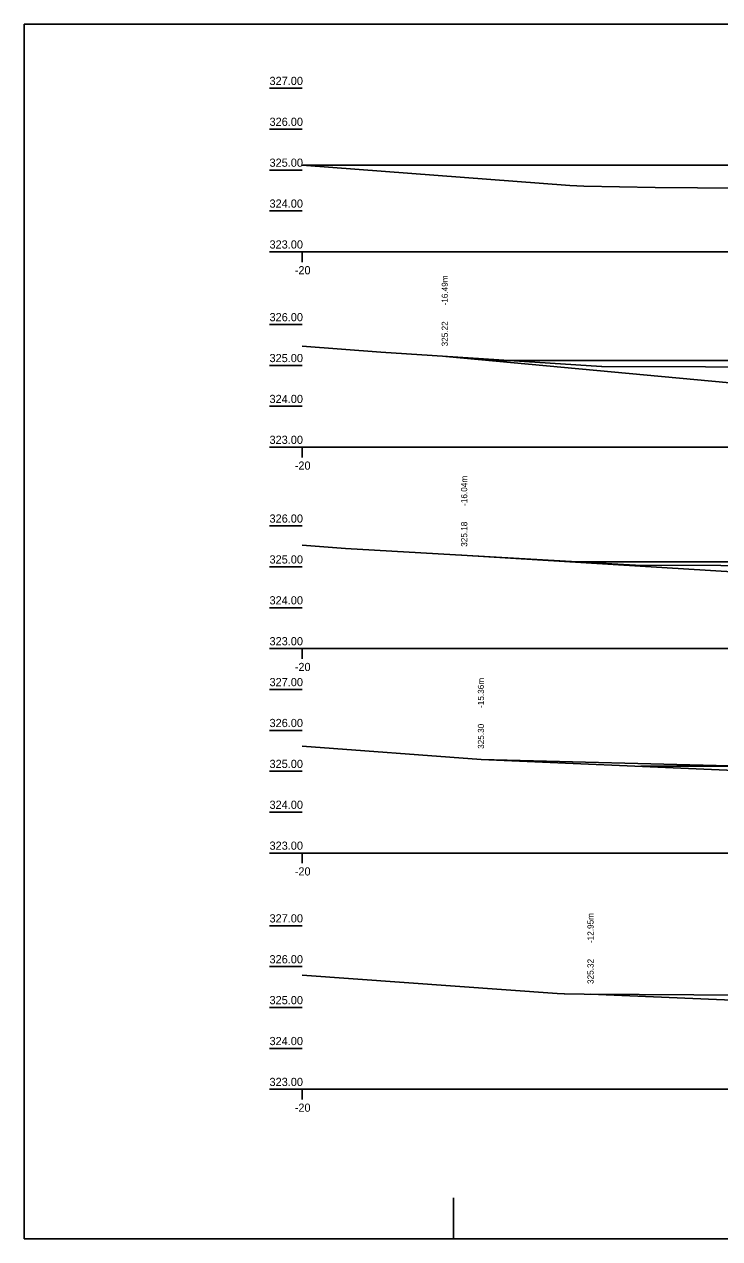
# Model space of a CAD drawing. Extents: x -557877.8 to -557804.3, y -1162285.8 to -1162256.1.
# Drawn here: x -557877.8 to -557860.8, y -1162285.8 to -1162256.1 of the extents above; entities that cross this region are included whole.
import ezdxf

# ---------------------------------------------------------------- set-up
doc = ezdxf.new("R2010")
doc.units = 0
for name, color, linetype in [('16', 7, 'Continuous'), ('21', 7, 'Continuous'), ('59', 7, 'Continuous'), ('Body pricny rez', 7, 'Continuous'), ('Popis pricneho profilu', 7, 'Continuous')]:
    doc.layers.add(name, color=color, linetype=linetype)

msp = doc.modelspace()

# ---------------------------------------------------------------- linework, layer by layer
for p, q in [((-557804.302, -1162256.102), (-557877.802, -1162256.102)), ((-557877.802, -1162256.102), (-557877.802, -1162285.802)), ((-557867.302, -1162285.802), (-557867.302, -1162284.802)), ((-557877.802, -1162285.802), (-557804.302, -1162285.802))]:
    msp.add_line(p, q)
for points in [[(-557871.005, -1162259.545), (-557864.464, -1162260.043), (-557864.118, -1162260.057), (-557862.37, -1162260.09), (-557859.263, -1162260.117), (-557856.183, -1162260.062), (-557856.133, -1162260.062), (-557856.051, -1162260.06), (-557848.291, -1162259.873), (-557847.829, -1162259.856), (-557840.415, -1162259.648), (-557840.07, -1162259.632), (-557832.415, -1162259.263), (-557831.005, -1162259.154)], [(-557870.994, -1162259.546), (-557838.275, -1162259.546)], [(-557871.005, -1162263.973), (-557869.084, -1162264.121), (-557863.687, -1162264.471), (-557863.682, -1162264.471), (-557861.146, -1162264.48), (-557859.312, -1162264.494), (-557859.307, -1162264.494), (-557857.717, -1162264.456), (-557856.24, -1162264.425), (-557852.539, -1162264.339), (-557848.349, -1162264.225), (-557844.087, -1162264.128), (-557840.375, -1162264.022), (-557836.581, -1162263.841), (-557832.414, -1162263.676), (-557831.005, -1162263.567)], [(-557854.045, -1162265.475), (-557867.49, -1162264.224)], [(-557866.422, -1162264.324), (-557839.401, -1162264.324)], [(-557871.005, -1162268.839), (-557869.944, -1162268.921), (-557862.864, -1162269.33), (-557862.864, -1162269.33), (-557862.858, -1162269.33), (-557860.77, -1162269.339), (-557859.335, -1162269.35), (-557859.329, -1162269.35), (-557857.423, -1162269.305), (-557856.259, -1162269.28), (-557853.342, -1162269.212), (-557848.362, -1162269.077), (-557843.297, -1162268.961), (-557840.368, -1162268.878), (-557837.376, -1162268.736), (-557832.408, -1162268.539), (-557831.005, -1162268.43)], [(-557854.281, -1162269.873), (-557867.102, -1162269.085)], [(-557864.436, -1162269.249), (-557841.875, -1162269.249)], [(-557871.005, -1162273.756), (-557866.633, -1162274.079), (-557866.633, -1162274.079), (-557866.626, -1162274.079), (-557860.248, -1162274.247), (-557859.367, -1162274.253), (-557859.359, -1162274.253), (-557857.014, -1162274.198), (-557856.286, -1162274.182), (-557854.46, -1162274.14), (-557848.38, -1162273.975), (-557842.196, -1162273.834), (-557840.359, -1162273.781), (-557838.482, -1162273.692), (-557832.4, -1162273.451), (-557831.005, -1162273.343)], [(-557854.611, -1162274.603), (-557866.633, -1162274.079)], [(-557862.728, -1162274.249), (-557841.132, -1162274.249)], [(-557871.005, -1162279.36), (-557864.773, -1162279.805), (-557864.6, -1162279.814), (-557864.591, -1162279.815), (-557864.11, -1162279.821), (-557860.084, -1162279.844), (-557860.076, -1162279.845), (-557857.908, -1162279.794), (-557856.326, -1162279.761), (-557848.559, -1162279.549), (-557848.413, -1162279.546), (-557848.274, -1162279.543), (-557840.34, -1162279.365), (-557839.969, -1162279.351), (-557832.396, -1162279.05), (-557831.005, -1162278.934)], [(-557855.288, -1162280.192), (-557863.955, -1162279.822)]]:
    msp.add_lwpolyline(points)
at = {"layer": '16'}
for p, q in [((-557871.005, -1162261.666), (-557831.005, -1162261.666)), ((-557871.005, -1162266.444), (-557831.005, -1162266.444)), ((-557871.005, -1162271.369), (-557831.005, -1162271.369)), ((-557871.005, -1162276.369), (-557831.005, -1162276.369)), ((-557871.005, -1162282.147), (-557831.005, -1162282.147))]:
    msp.add_line(p, q, dxfattribs=at)
at = {"layer": '21'}
for p, q in [((-557871.805, -1162257.666), (-557871.005, -1162257.666)), ((-557871.805, -1162258.666), (-557871.005, -1162258.666)), ((-557871.805, -1162259.666), (-557871.005, -1162259.666)), ((-557871.805, -1162260.666), (-557871.005, -1162260.666)), ((-557871.805, -1162261.666), (-557871.005, -1162261.666)), ((-557871.805, -1162263.444), (-557871.005, -1162263.444)), ((-557871.805, -1162264.444), (-557871.005, -1162264.444)), ((-557871.805, -1162265.444), (-557871.005, -1162265.444)), ((-557871.805, -1162266.444), (-557871.005, -1162266.444)), ((-557871.805, -1162268.369), (-557871.005, -1162268.369)), ((-557871.805, -1162269.369), (-557871.005, -1162269.369)), ((-557871.805, -1162270.369), (-557871.005, -1162270.369)), ((-557871.805, -1162271.369), (-557871.005, -1162271.369)), ((-557871.805, -1162272.369), (-557871.005, -1162272.369)), ((-557871.805, -1162273.369), (-557871.005, -1162273.369)), ((-557871.805, -1162274.369), (-557871.005, -1162274.369)), ((-557871.805, -1162275.369), (-557871.005, -1162275.369)), ((-557871.805, -1162276.369), (-557871.005, -1162276.369)), ((-557871.805, -1162278.147), (-557871.005, -1162278.147)), ((-557871.805, -1162279.147), (-557871.005, -1162279.147)), ((-557871.805, -1162280.147), (-557871.005, -1162280.147)), ((-557871.805, -1162281.147), (-557871.005, -1162281.147)), ((-557871.805, -1162282.147), (-557871.005, -1162282.147))]:
    msp.add_line(p, q, dxfattribs=at)
at = {"layer": '59'}
for p, q in [((-557871.005, -1162261.916), (-557871.005, -1162261.666)), ((-557871.005, -1162266.694), (-557871.005, -1162266.444)), ((-557871.005, -1162271.619), (-557871.005, -1162271.369)), ((-557871.005, -1162276.619), (-557871.005, -1162276.369)), ((-557871.005, -1162282.397), (-557871.005, -1162282.147))]:
    msp.add_line(p, q, dxfattribs=at)

# ---------------------------------------------------------------- texts
at = {"layer": '21'}
for s, p in [('327.00', (-557871.805, -1162257.586)), ('326.00', (-557871.805, -1162258.586)), ('325.00', (-557871.805, -1162259.586)), ('324.00', (-557871.805, -1162260.586)), ('323.00', (-557871.805, -1162261.586)), ('-20', (-557871.188, -1162262.216)), ('326.00', (-557871.805, -1162263.364)), ('325.00', (-557871.805, -1162264.364)), ('324.00', (-557871.805, -1162265.364)), ('323.00', (-557871.805, -1162266.364)), ('-20', (-557871.188, -1162266.994)), ('326.00', (-557871.805, -1162268.289)), ('325.00', (-557871.805, -1162269.289)), ('324.00', (-557871.805, -1162270.289)), ('323.00', (-557871.805, -1162271.289)), ('-20', (-557871.188, -1162271.919)), ('327.00', (-557871.805, -1162272.289)), ('326.00', (-557871.805, -1162273.289)), ('325.00', (-557871.805, -1162274.289)), ('324.00', (-557871.805, -1162275.289)), ('323.00', (-557871.805, -1162276.289)), ('-20', (-557871.188, -1162276.919)), ('327.00', (-557871.805, -1162278.067)), ('326.00', (-557871.805, -1162279.067)), ('325.00', (-557871.805, -1162280.067)), ('324.00', (-557871.805, -1162281.067)), ('323.00', (-557871.805, -1162282.067)), ('-20', (-557871.188, -1162282.697))]:
    msp.add_text(s, height=0.2, dxfattribs=at).set_placement(p)
at = {"layer": 'Body pricny rez'}
for p in [(-557869.586, -1162259.653), (-557869.586, -1162259.653), (-557867.045, -1162269.131), (-557867.045, -1162269.131)]:
    msp.add_text('+', height=0.001, dxfattribs=at).set_placement(p)
at = {"layer": 'Popis pricneho profilu'}
for s, p in [('-16.49m', (-557867.445, -1162262.979)), ('325.22', (-557867.445, -1162263.979)), ('-16.04m', (-557866.97, -1162267.88)), ('325.18', (-557866.97, -1162268.88)), ('-15.36m', (-557866.56, -1162272.822)), ('325.30', (-557866.56, -1162273.822)), ('-12.95m', (-557863.88, -1162278.572)), ('325.32', (-557863.88, -1162279.572))]:
    msp.add_text(s, height=0.15, rotation=90, dxfattribs=at).set_placement(p)

doc.saveas('drawing.dxf')
